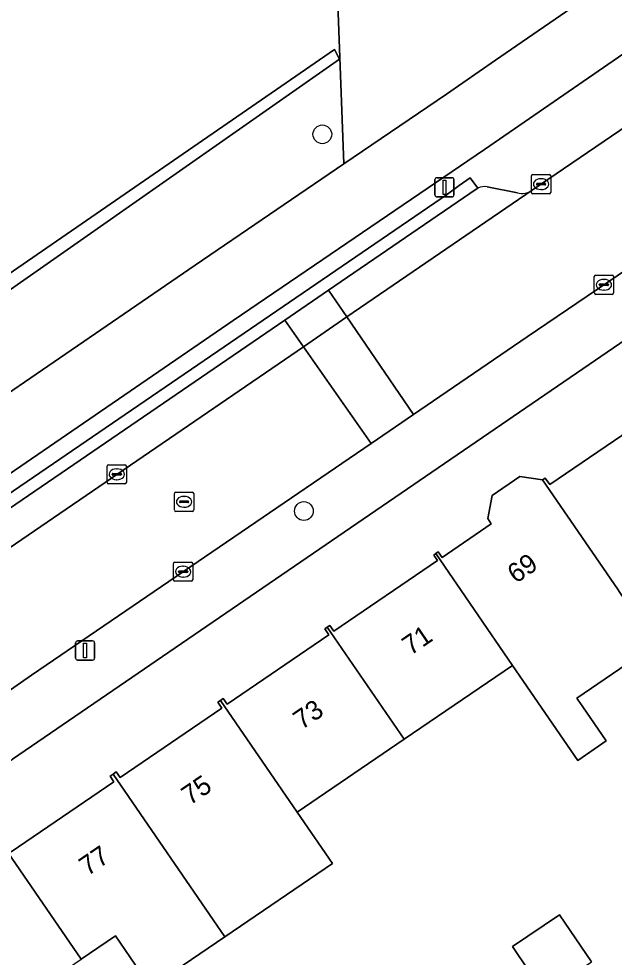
# Model space of a CAD drawing. Extents: x 157445 to 158888, y 383061 to 384688.
# Drawn here: x 158061.82 to 158092.84, y 383863.07 to 383911.91 of the extents above; entities that cross this region are included whole.
import ezdxf

# ---------------------------------------------------------------- set-up
doc = ezdxf.new("R2010")
doc.units = 0
for name, color, linetype in [('IMGEO_Boom', 7, 'Continuous'), ('IMGEO_Erf', 7, 'Continuous'), ('IMGEO_Fietspad_gesloten', 7, 'Continuous'), ('IMGEO_Greppel_droge_sloot', 7, 'Continuous'), ('IMGEO_Groenvoorziening', 7, 'Continuous'), ('IMGEO_Kolk', 7, 'Continuous'), ('IMGEO_Lichtmast', 7, 'Continuous'), ('IMGEO_Pand', 7, 'Continuous'), ('IMGEO_Pand_nummerreeks', 7, 'Continuous'), ('IMGEO_Parkeervlak_open', 7, 'Continuous'), ('IMGEO_Rijbaan_lokaal_open', 7, 'Continuous'), ('IMGEO_Rioolput', 7, 'Continuous'), ('IMGEO_Voetpad_open', 7, 'Continuous')]:
    doc.layers.add(name, color=color, linetype=linetype)

msp = doc.modelspace()

# ---------------------------------------------------------------- linework, layer by layer
at = {"layer": 'IMGEO_Boom'}
for centre in [(158077.635, 383905.898), (158076.673, 383886.295)]:
    msp.add_circle(centre, 0.489, dxfattribs=at)
at = {"layer": 'IMGEO_Erf'}
for points in [[(158094.454, 383895.908), (158061.486, 383873.374)], [(158061.425, 383868.557), (158066.779, 383872.2), (158066.577, 383872.496), (158066.738, 383872.605), (158066.899, 383872.715), (158067.096, 383872.424), (158072.4, 383876.032), (158072.187, 383876.345), (158072.328, 383876.441), (158072.469, 383876.537), (158072.671, 383876.24), (158077.981, 383879.852), (158077.765, 383880.17), (158077.892, 383880.257), (158078.021, 383880.344), (158078.229, 383880.038), (158083.632, 383883.715), (158083.435, 383884.005), (158083.554, 383884.086), (158083.673, 383884.166), (158083.869, 383883.879), (158086.432, 383885.623), (158086.259, 383885.898), (158086.49, 383887.107), (158087.922, 383888.099), (158089.11, 383887.918), (158089.249, 383888.012), (158089.478, 383887.675), (158094.916, 383891.375)], [(158094.988, 383879.349), (158090.896, 383876.554), (158090.97, 383876.446), (158091.208, 383876.1), (158092.423, 383874.329), (158090.943, 383873.315), (158087.548, 383878.264), (158081.898, 383874.419), (158076.32, 383870.624), (158078.157, 383867.947), (158072.551, 383864.133), (158069.521, 383862.071)], [(158089.208, 383861.148), (158087.542, 383863.625), (158089.992, 383865.272), (158091.665, 383862.833)], [(158068.132, 383862.335), (158066.868, 383864.194), (158065.07, 383862.97)]]:
    msp.add_lwpolyline(points, dxfattribs=at)
at = {"layer": 'IMGEO_Fietspad_gesloten'}
for points in [[(158109.226, 383927.034), (158107.59, 383924.773), (158105.598, 383922.996), (158096.199, 383916.329), (158086.66, 383909.753), (158084.107, 383907.993), (158078.757, 383904.358), (158071.011, 383899.096), (158058.725, 383890.695), (158043.835, 383880.614)], [(158045.888, 383877.777), (158060.694, 383887.801), (158072.982, 383896.204), (158086.084, 383905.105), (158098.205, 383913.461), (158107.782, 383920.254), (158110.203, 383922.414), (158112.062, 383924.982)]]:
    msp.add_lwpolyline(points, dxfattribs=at)
at = {"layer": 'IMGEO_Greppel_droge_sloot'}
msp.add_lwpolyline([(158034.345, 383880.083), (158031.419, 383877.938), (158031.901, 383877.207), (158078.524, 383909.804), (158078.272, 383910.309)], close=True, dxfattribs=at)
at = {"layer": 'IMGEO_Groenvoorziening'}
for points in [[(158117.884, 383996.348), (158118.245, 383996.636), (158114.905, 383996.74), (158110.102, 383996.889), (158101.048, 383990.352), (158092.657, 383982.959), (158098.721, 383937.84), (158078.046, 383923.492), (158078.5, 383911.281), (158078.757, 383904.358), (158084.107, 383907.993), (158086.66, 383909.753), (158096.199, 383916.329), (158105.598, 383922.996), (158107.59, 383924.773), (158109.226, 383927.034)], [(158043.835, 383880.614), (158058.725, 383890.695), (158071.011, 383899.096), (158078.757, 383904.358), (158078.5, 383911.281), (158078.046, 383923.492), (158098.721, 383937.84), (158092.657, 383982.959)], [(158112.062, 383924.982), (158110.203, 383922.414), (158107.782, 383920.254), (158098.205, 383913.461), (158086.084, 383905.105), (158072.982, 383896.204), (158060.694, 383887.801), (158045.888, 383877.777)], [(158088.566, 383902.987), (158093.943, 383906.66), (158103.038, 383912.884)], [(158043.991, 383874.151), (158045.268, 383875.113), (158046.53, 383876.836), (158046.8, 383877.178), (158047.146, 383877.527), (158084.153, 383902.776), (158084.77, 383903.228), (158085.335, 383903.642), (158085.734, 383903.096)], [(158086.23, 383903.165), (158087.797, 383902.845)]]:
    msp.add_lwpolyline(points, dxfattribs=at)
msp.add_lwpolyline([(158078.272, 383910.309), (158078.524, 383909.804), (158031.901, 383877.207), (158031.419, 383877.938), (158034.345, 383880.083)], close=True, dxfattribs=at)
for centre, radius, start, end in [((158086.081, 383902.419), 0.761, 78.7071, 117.1324), ((158088.018, 383903.801), 0.981, 256.9692, 303.9551)]:
    msp.add_arc(centre, radius, start, end, dxfattribs=at)
at = {"layer": 'IMGEO_Kolk'}
for p, q in [((158088.604, 383903.805), (158089.456, 383903.805)), ((158088.529, 383902.879), (158088.529, 383903.731)), ((158088.788, 383903.299), (158088.788, 383903.311)), ((158088.831, 383903.348), (158089.229, 383903.348)), ((158089.017, 383903.585), (158089.042, 383903.585)), ((158089.272, 383903.311), (158089.272, 383903.299)), ((158089.53, 383903.731), (158089.53, 383902.879)), ((158089.226, 383903.262), (158088.828, 383903.262)), ((158089.04, 383903.025), (158089.015, 383903.025)), ((158089.456, 383902.805), (158088.604, 383902.805)), ((158091.803, 383897.644), (158091.803, 383898.496)), ((158091.878, 383898.57), (158092.73, 383898.57)), ((158092.804, 383898.496), (158092.804, 383897.644)), ((158092.062, 383898.064), (158092.062, 383898.076)), ((158092.5, 383898.027), (158092.102, 383898.027)), ((158092.105, 383898.113), (158092.503, 383898.113)), ((158092.291, 383898.35), (158092.316, 383898.35)), ((158092.546, 383898.076), (158092.546, 383898.064)), ((158092.73, 383897.57), (158091.878, 383897.57)), ((158092.314, 383897.79), (158092.289, 383897.79)), ((158066.501, 383888.706), (158067.353, 383888.706)), ((158066.426, 383887.78), (158066.426, 383888.632)), ((158066.685, 383888.2), (158066.685, 383888.212)), ((158067.123, 383888.163), (158066.725, 383888.163)), ((158066.728, 383888.249), (158067.126, 383888.249)), ((158066.914, 383888.486), (158066.939, 383888.486)), ((158067.169, 383888.212), (158067.169, 383888.2)), ((158067.427, 383888.632), (158067.427, 383887.78)), ((158067.353, 383887.706), (158066.501, 383887.706)), ((158066.937, 383887.926), (158066.912, 383887.926)), ((158069.883, 383882.713), (158069.883, 383883.565)), ((158069.958, 383883.639), (158070.81, 383883.639)), ((158070.371, 383883.419), (158070.396, 383883.419)), ((158070.884, 383883.565), (158070.884, 383882.713)), ((158070.142, 383883.133), (158070.142, 383883.145)), ((158070.58, 383883.096), (158070.182, 383883.096)), ((158070.185, 383883.182), (158070.583, 383883.182)), ((158070.394, 383882.859), (158070.369, 383882.859)), ((158070.626, 383883.145), (158070.626, 383883.133)), ((158070.81, 383882.639), (158069.958, 383882.639))]:
    msp.add_line(p, q, dxfattribs=at)
for points in [[(158088.604, 383903.805), (158089.456, 383903.805)], [(158088.529, 383902.879), (158088.529, 383903.731)], [(158089.53, 383903.731), (158089.53, 383902.879)], [(158089.456, 383902.805), (158088.604, 383902.805)], [(158091.803, 383897.644), (158091.803, 383898.496)], [(158091.878, 383898.57), (158092.73, 383898.57)], [(158092.804, 383898.496), (158092.804, 383897.644)], [(158092.73, 383897.57), (158091.878, 383897.57)], [(158066.501, 383888.706), (158067.353, 383888.706)], [(158066.426, 383887.78), (158066.426, 383888.632)], [(158067.427, 383888.632), (158067.427, 383887.78)], [(158067.353, 383887.706), (158066.501, 383887.706)], [(158069.883, 383882.713), (158069.883, 383883.565)], [(158069.958, 383883.639), (158070.81, 383883.639)], [(158070.884, 383883.565), (158070.884, 383882.713)], [(158070.81, 383882.639), (158069.958, 383882.639)]]:
    msp.add_lwpolyline(points, dxfattribs=at)
for centre, radius, start, end in [((158088.606, 383903.729), 0.0765, 91.552, 178.448), ((158088.606, 383903.729), 0.0765, 91.552, 178.448), ((158089.454, 383903.729), 0.0765, 1.552, 88.448), ((158089.454, 383903.729), 0.0765, 1.552, 88.448), ((158088.828, 383903.308), 0.0403, 85.8775, 175.7526), ((158088.825, 383903.298), 0.0366, 178.938, 274.7102), ((158089.229, 383903.305), 0.043, 264.8664, 352.4533), ((158089.233, 383903.31), 0.0386, 1.7309, 96.639), ((158088.606, 383902.881), 0.0765, 181.552, 268.448), ((158088.606, 383902.881), 0.0765, 181.552, 268.448), ((158089.454, 383902.881), 0.0765, 271.552, 358.448), ((158089.454, 383902.881), 0.0765, 271.552, 358.448), ((158091.88, 383898.494), 0.0765, 91.552, 178.448), ((158091.88, 383898.494), 0.0765, 91.552, 178.448), ((158092.728, 383898.494), 0.0765, 1.552, 88.448), ((158092.728, 383898.494), 0.0765, 1.552, 88.448), ((158092.102, 383898.073), 0.0403, 85.8775, 175.7526), ((158092.099, 383898.063), 0.0366, 178.938, 274.7102), ((158092.503, 383898.07), 0.043, 264.8664, 352.4533), ((158092.507, 383898.075), 0.0386, 1.7309, 96.639), ((158091.88, 383897.646), 0.0765, 181.552, 268.448), ((158091.88, 383897.646), 0.0765, 181.552, 268.448), ((158092.728, 383897.646), 0.0765, 271.552, 358.448), ((158092.728, 383897.646), 0.0765, 271.552, 358.448), ((158066.503, 383888.63), 0.0765, 91.552, 178.448), ((158066.503, 383888.63), 0.0765, 91.552, 178.448), ((158067.351, 383888.63), 0.0765, 1.552, 88.448), ((158067.351, 383888.63), 0.0765, 1.552, 88.448), ((158066.725, 383888.209), 0.0403, 85.8775, 175.7526), ((158066.722, 383888.199), 0.0366, 178.938, 274.7102), ((158067.126, 383888.206), 0.043, 264.8664, 352.4533), ((158067.13, 383888.211), 0.0386, 1.7309, 96.639), ((158066.503, 383887.782), 0.0765, 181.552, 268.448), ((158066.503, 383887.782), 0.0765, 181.552, 268.448), ((158067.351, 383887.782), 0.0765, 271.552, 358.448), ((158067.351, 383887.782), 0.0765, 271.552, 358.448), ((158069.96, 383883.563), 0.0765, 91.552, 178.448), ((158069.96, 383883.563), 0.0765, 91.552, 178.448), ((158070.808, 383883.563), 0.0765, 1.552, 88.448), ((158070.808, 383883.563), 0.0765, 1.552, 88.448), ((158070.182, 383883.142), 0.0403, 85.8775, 175.7526), ((158070.179, 383883.132), 0.0366, 178.938, 274.7102), ((158070.583, 383883.139), 0.043, 264.8664, 352.4533), ((158070.587, 383883.144), 0.0386, 1.7309, 96.639), ((158069.96, 383882.715), 0.0765, 181.552, 268.448), ((158069.96, 383882.715), 0.0765, 181.552, 268.448), ((158070.808, 383882.715), 0.0765, 271.552, 358.448), ((158070.808, 383882.715), 0.0765, 271.552, 358.448)]:
    msp.add_arc(centre, radius, start, end, dxfattribs=at)
for centre, major_axis, ratio, start_param, end_param in [((158089.016, 383903.305), (-0.387, 0.002), 0.722429, 4.712389, 7.853982), ((158089.041, 383903.305), (-0.39, 0.002), 0.717154, 1.570796, 4.712389), ((158092.29, 383898.07), (-0.387, 0.002), 0.722429, 4.712389, 7.853982), ((158092.315, 383898.07), (-0.39, 0.002), 0.717154, 1.570796, 4.712389), ((158066.913, 383888.206), (-0.387, 0.002), 0.722429, 4.712389, 7.853982), ((158066.938, 383888.206), (-0.39, 0.002), 0.717154, 1.570796, 4.712389), ((158070.37, 383883.139), (-0.387, 0.002), 0.722429, 4.712389, 7.853982), ((158070.395, 383883.139), (-0.39, 0.002), 0.717154, 1.570796, 4.712389)]:
    msp.add_ellipse(centre, major_axis=major_axis, ratio=ratio, start_param=start_param, end_param=end_param, dxfattribs=at)
at = {"layer": 'IMGEO_Lichtmast'}
for p, q in [((158083.501, 383902.742), (158083.501, 383903.542)), ((158083.501, 383903.542), (158083.501, 383902.742)), ((158083.601, 383903.642), (158084.391, 383903.642)), ((158084.391, 383903.642), (158083.601, 383903.642)), ((158084.491, 383903.542), (158084.491, 383902.742)), ((158084.491, 383902.742), (158084.491, 383903.542)), ((158084.391, 383902.642), (158083.601, 383902.642)), ((158083.601, 383902.642), (158084.391, 383902.642)), ((158064.78, 383878.635), (158064.78, 383879.435)), ((158064.78, 383879.435), (158064.78, 383878.635)), ((158064.88, 383879.535), (158065.67, 383879.535)), ((158065.67, 383879.535), (158064.88, 383879.535)), ((158065.77, 383879.435), (158065.77, 383878.635)), ((158065.77, 383878.635), (158065.77, 383879.435)), ((158065.67, 383878.535), (158064.88, 383878.535)), ((158064.88, 383878.535), (158065.67, 383878.535))]:
    msp.add_line(p, q, dxfattribs=at)
for points in [[(158083.921, 383903.517), (158084.071, 383903.517), (158084.071, 383902.767), (158083.921, 383902.767), (158083.921, 383903.517)], [(158065.2, 383879.41), (158065.35, 383879.41), (158065.35, 383878.66), (158065.2, 383878.66), (158065.2, 383879.41)]]:
    msp.add_lwpolyline(points, dxfattribs=at)
for centre, start, end in [((158083.601, 383903.542), 90, 180), ((158083.601, 383903.542), 90, 180), ((158084.391, 383903.542), 0, 90), ((158084.391, 383903.542), 360, 90), ((158083.601, 383902.742), 180, 270), ((158083.601, 383902.742), 180, 270), ((158084.391, 383902.742), 270, 0), ((158084.391, 383902.742), 270, 0), ((158064.88, 383879.435), 90, 180), ((158064.88, 383879.435), 90, 180), ((158065.67, 383879.435), 0, 90), ((158065.67, 383879.435), 360, 90), ((158064.88, 383878.635), 180, 270), ((158064.88, 383878.635), 180, 270), ((158065.67, 383878.635), 270, 0), ((158065.67, 383878.635), 270, 0)]:
    msp.add_arc(centre, 0.1, start, end, dxfattribs=at)
at = {"layer": 'IMGEO_Pand'}
for points in [[(158097.734, 383887.922), (158101.036, 383890.178), (158098.294, 383894.19), (158098.039, 383894.016), (158098.231, 383893.736), (158095.139, 383891.616), (158094.946, 383891.896), (158094.683, 383891.717), (158094.916, 383891.375), (158089.478, 383887.675), (158089.249, 383888.012), (158089.11, 383887.918), (158093.007, 383882.238), (158093.128, 383882.061), (158094.988, 383879.349), (158096.726, 383880.536), (158100.854, 383883.356)], [(158089.11, 383887.918), (158087.922, 383888.099), (158086.49, 383887.107), (158086.259, 383885.898), (158086.432, 383885.623), (158083.869, 383883.879), (158083.673, 383884.166), (158083.554, 383884.086), (158087.548, 383878.264), (158090.943, 383873.315), (158092.423, 383874.329), (158091.208, 383876.1), (158090.97, 383876.446), (158090.896, 383876.554), (158094.988, 383879.349), (158093.128, 383882.061), (158093.007, 383882.238)], [(158077.892, 383880.257), (158081.898, 383874.419), (158087.548, 383878.264), (158083.554, 383884.086), (158083.435, 383884.005), (158083.632, 383883.715), (158078.229, 383880.038), (158078.021, 383880.344)], [(158077.892, 383880.257), (158077.765, 383880.17), (158077.981, 383879.852), (158072.671, 383876.24), (158072.469, 383876.537), (158072.328, 383876.441), (158076.32, 383870.624), (158081.898, 383874.419)], [(158072.328, 383876.441), (158072.187, 383876.345), (158072.4, 383876.032), (158067.096, 383872.424), (158066.899, 383872.715), (158066.738, 383872.605), (158072.551, 383864.133), (158078.157, 383867.947), (158076.32, 383870.624)], [(158065.07, 383862.97), (158066.868, 383864.194), (158068.132, 383862.335), (158069.521, 383862.071), (158072.551, 383864.133), (158066.738, 383872.605), (158066.577, 383872.496), (158066.779, 383872.2), (158061.425, 383868.557), (158061.205, 383868.879), (158061.076, 383868.791)], [(158061.076, 383868.791), (158060.946, 383868.703), (158061.182, 383868.356), (158055.876, 383864.746), (158055.68, 383865.034), (158055.396, 383864.84), (158055.62, 383864.511), (158053.344, 383863.033), (158057.27, 383857.315), (158059.482, 383858.835), (158059.563, 383858.716), (158059.847, 383858.909), (158059.611, 383859.256), (158063.745, 383862.069), (158065.07, 383862.97)], [(158089.208, 383861.148), (158091.665, 383862.833), (158089.992, 383865.272), (158087.542, 383863.625)]]:
    msp.add_lwpolyline(points, close=True, dxfattribs=at)
at = {"layer": 'IMGEO_Parkeervlak_open'}
for points in [[(158085.734, 383903.096), (158085.657, 383903.05), (158077.954, 383897.788), (158078.912, 383896.392), (158088.566, 383902.987)], [(158087.797, 383902.845), (158086.23, 383903.165)], [(158045.792, 383873.594), (158046.236, 383873.9), (158057.614, 383881.843), (158076.648, 383894.846), (158075.677, 383896.232), (158056.658, 383883.24), (158047.1, 383876.687)]]:
    msp.add_lwpolyline(points, dxfattribs=at)
msp.add_lwpolyline([(158077.954, 383897.788), (158075.677, 383896.232), (158076.648, 383894.846), (158078.912, 383896.392)], close=True, dxfattribs=at)
for centre, radius, start, end in [((158086.081, 383902.419), 0.761, 78.7071, 117.1324), ((158088.018, 383903.801), 0.981, 256.9692, 303.9551)]:
    msp.add_arc(centre, radius, start, end, dxfattribs=at)
at = {"layer": 'IMGEO_Rijbaan_lokaal_open'}
for points in [[(158135.426, 383927.536), (158131.852, 383932.606), (158103.038, 383912.884), (158093.943, 383906.66), (158088.566, 383902.987), (158078.912, 383896.392), (158082.388, 383891.324), (158088.313, 383895.363), (158095.088, 383899.962), (158102.711, 383905.136), (158106.703, 383907.846)], [(158082.388, 383891.324), (158078.912, 383896.392), (158076.648, 383894.846), (158080.174, 383889.815)]]:
    msp.add_lwpolyline(points, close=True, dxfattribs=at)
for points in [[(158080.174, 383889.815), (158076.648, 383894.846), (158057.614, 383881.843), (158046.236, 383873.9), (158045.792, 383873.594), (158045.141, 383873.146)], [(158051.626, 383870.258), (158058.509, 383874.995), (158062.486, 383877.757), (158080.174, 383889.815)]]:
    msp.add_lwpolyline(points, dxfattribs=at)
at = {"layer": 'IMGEO_Rioolput'}
for p, q in [((158069.932, 383886.348), (158069.932, 383887.2)), ((158070.007, 383887.274), (158070.859, 383887.274)), ((158070.933, 383887.2), (158070.933, 383886.348)), ((158070.191, 383886.768), (158070.191, 383886.78)), ((158070.629, 383886.731), (158070.231, 383886.731)), ((158070.234, 383886.817), (158070.632, 383886.817)), ((158070.42, 383887.054), (158070.445, 383887.054)), ((158070.675, 383886.78), (158070.675, 383886.768)), ((158070.859, 383886.274), (158070.007, 383886.274)), ((158070.443, 383886.494), (158070.418, 383886.494))]:
    msp.add_line(p, q, dxfattribs=at)
for points in [[(158069.932, 383886.348), (158069.932, 383887.2)], [(158070.007, 383887.274), (158070.859, 383887.274)], [(158070.933, 383887.2), (158070.933, 383886.348)], [(158070.859, 383886.274), (158070.007, 383886.274)]]:
    msp.add_lwpolyline(points, dxfattribs=at)
for centre, radius, start, end in [((158070.009, 383887.198), 0.0765, 91.552, 178.448), ((158070.009, 383887.198), 0.0765, 91.552, 178.448), ((158070.857, 383887.198), 0.0765, 1.552, 88.448), ((158070.857, 383887.198), 0.0765, 1.552, 88.448), ((158070.231, 383886.777), 0.0403, 85.8775, 175.7526), ((158070.228, 383886.767), 0.0366, 178.938, 274.7102), ((158070.632, 383886.774), 0.043, 264.8664, 352.4533), ((158070.636, 383886.779), 0.0386, 1.7309, 96.639), ((158070.009, 383886.35), 0.0765, 181.552, 268.448), ((158070.009, 383886.35), 0.0765, 181.552, 268.448), ((158070.857, 383886.35), 0.0765, 271.552, 358.448), ((158070.857, 383886.35), 0.0765, 271.552, 358.448)]:
    msp.add_arc(centre, radius, start, end, dxfattribs=at)
for centre, major_axis, ratio, start_param, end_param in [((158070.419, 383886.774), (-0.387, 0.002), 0.722429, 4.712389, 7.853982), ((158070.444, 383886.774), (-0.39, 0.002), 0.717154, 1.570796, 4.712389)]:
    msp.add_ellipse(centre, major_axis=major_axis, ratio=ratio, start_param=start_param, end_param=end_param, dxfattribs=at)
at = {"layer": 'IMGEO_Voetpad_open'}
for points in [[(158094.454, 383895.908), (158099.331, 383899.321), (158102.377, 383901.408), (158103.318, 383904.242), (158095.695, 383899.068), (158095.088, 383899.962), (158088.313, 383895.363), (158082.388, 383891.324), (158080.174, 383889.815), (158062.486, 383877.757), (158058.509, 383874.995), (158051.626, 383870.258)], [(158047.1, 383876.687), (158056.658, 383883.24), (158075.677, 383896.232), (158077.954, 383897.788), (158085.657, 383903.05), (158085.734, 383903.096), (158085.335, 383903.642), (158084.77, 383903.228), (158084.153, 383902.776), (158047.146, 383877.527), (158046.8, 383877.178), (158046.53, 383876.836), (158045.268, 383875.113), (158043.991, 383874.151)], [(158049.567, 383867.819), (158052.526, 383864.224), (158052.925, 383867.553), (158061.486, 383873.374), (158094.454, 383895.908)]]:
    msp.add_lwpolyline(points, dxfattribs=at)

# ---------------------------------------------------------------- texts
at = {"layer": 'IMGEO_Pand_nummerreeks'}
for s, rotation, p in [('69', 34.2973, (158087.716, 383882.493)), ('71', 34.2977, (158082.232, 383878.753)), ('73', 34.2977, (158076.562, 383874.885)), ('75', 34.2977, (158070.736, 383870.954)), ('77', 34.2977, (158065.408, 383867.276))]:
    msp.add_text(s, height=1, rotation=rotation, dxfattribs=at).set_placement(p)

doc.saveas('drawing.dxf')
